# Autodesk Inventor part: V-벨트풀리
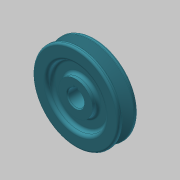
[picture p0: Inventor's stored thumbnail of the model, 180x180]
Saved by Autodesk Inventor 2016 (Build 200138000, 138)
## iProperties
Created: 2019-01
Part Number: V-벨트풀리
Material: 알루미늄 6061
Document SubType Name: Modeling
Designer: mduedu
Density: 1 g/cm^3
Appearance: 커뎃 파란색
Author: mduedu
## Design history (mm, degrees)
sketch "스케치1"
  geometry: L1 (-10, 0)-(10, 0); L2 (10, 0)-(10, 44.5); L3 (10, 44.5)-(-10, 44.5); L4 (-10, 44.5)-(-10, 0); L5 (0, 0)-(0, 44.5); L6 (-5.976, 44.5)-(-2.154, 32); L7 (-2.154, 32)-(2.154, 32); L8 (2.154, 32)-(5.976, 44.5); L9 (-10, 40)-(10, 40); 3 further points
  constraints: 18 end point, 8 point on line, 3 perpendicular, 2 midpoint, 2 parallel, 1 coincident, 1 horizontal, 1 other
  dimensions: "d0" = 89 diameter of L3 L1; "d2" = 20 distance of L2.end L3.end; "d3" = 34 deg angle of L8 L6; "d4" = 9.2 distance of point (4.6, 40) point (-4.6, 40); "d5" = 80 diameter of L9 L1; "d6" = 8 distance between parallel lines of L7 L9; "d7" = 4.5 distance between parallel lines of L3 L9 (derived)
revolve "회전1" sketch "스케치1" stored, may be unused: angle "d8" = 90 deg
fillet "모깎기1" dims "d9" = 0.5, "d10" = 1, "d11" = 2
sketch "스케치2"
  geometry: C1 r 17.5 at (0, 0); 1 further point
  constraints: 1 centre point, 1 coincident
  dimensions: "d12" = 35 diameter of C1
extrude "돌출1" join sketch "스케치2" distance "d13" = 10; taper "d14" = 0 deg
sketch "스케치3"
  geometry: L1 (-2.5, 8.124)-(2.5, 8.124); L2 (2.5, 8.124)-(2.5, 10.8); L3 (2.5, 10.8)-(-2.5, 10.8); L4 (-2.5, 10.8)-(-2.5, 8.124); A1 r 8.5 centre (0, 0) between (-2.5, 8.124) and (2.5, 8.124); 1 further point
  constraints: 8 end point, 2 parallel, 2 point on circle, 1 centre point, 1 coincident, 1 horizontal, 1 perpendicular
  dimensions: "d15" = 17 diameter of A1; "d16" = 5 distance of L2.end L3.end; "d17" = 19.3 dimension on A1 L3
extrude "돌출2" cut sketch "스케치3" stored distance "d18" = 10; taper "d19" = 0 deg
node "작업 평면1"
sketch "스케치4"
  geometry: L1 (-10, 17.5)-(-10, -17.5) reference; 2 further points
  constraints: 1 horizontal alignment
  dimensions: "d21" = 8 distance from line of point (-2, 0) L1
hole "구멍1" sketch "스케치4" at (-2, 0) diameter "d22" = 2.459; stored, may be unused: countersink angle "d26" = 90 deg, drill point angle "d28" = 118 deg; dims "d23" = 6, "d24" = 4, "d25" = 2, "d27" = 8
chamfer "모따기1" distance "d29" = 1; stored, may be unused: second distance "d30" = 2, angle "d31" = 45 deg
sketch "스케치5"
  geometry: C1 r 17.5 at (0, 0) reference; C2 r 30 at (0, 0); 1 further point
  constraints: 1 centre point, 1 coincident
  dimensions: "d37" = 60 diameter of C2
extrude "돌출3" cut sketch "스케치5" distance "d34" = 6; taper "d35" = 0 deg
fillet "모깎기4" dims "d38" = 3
node "솔리드1"
mirror "대칭1"
